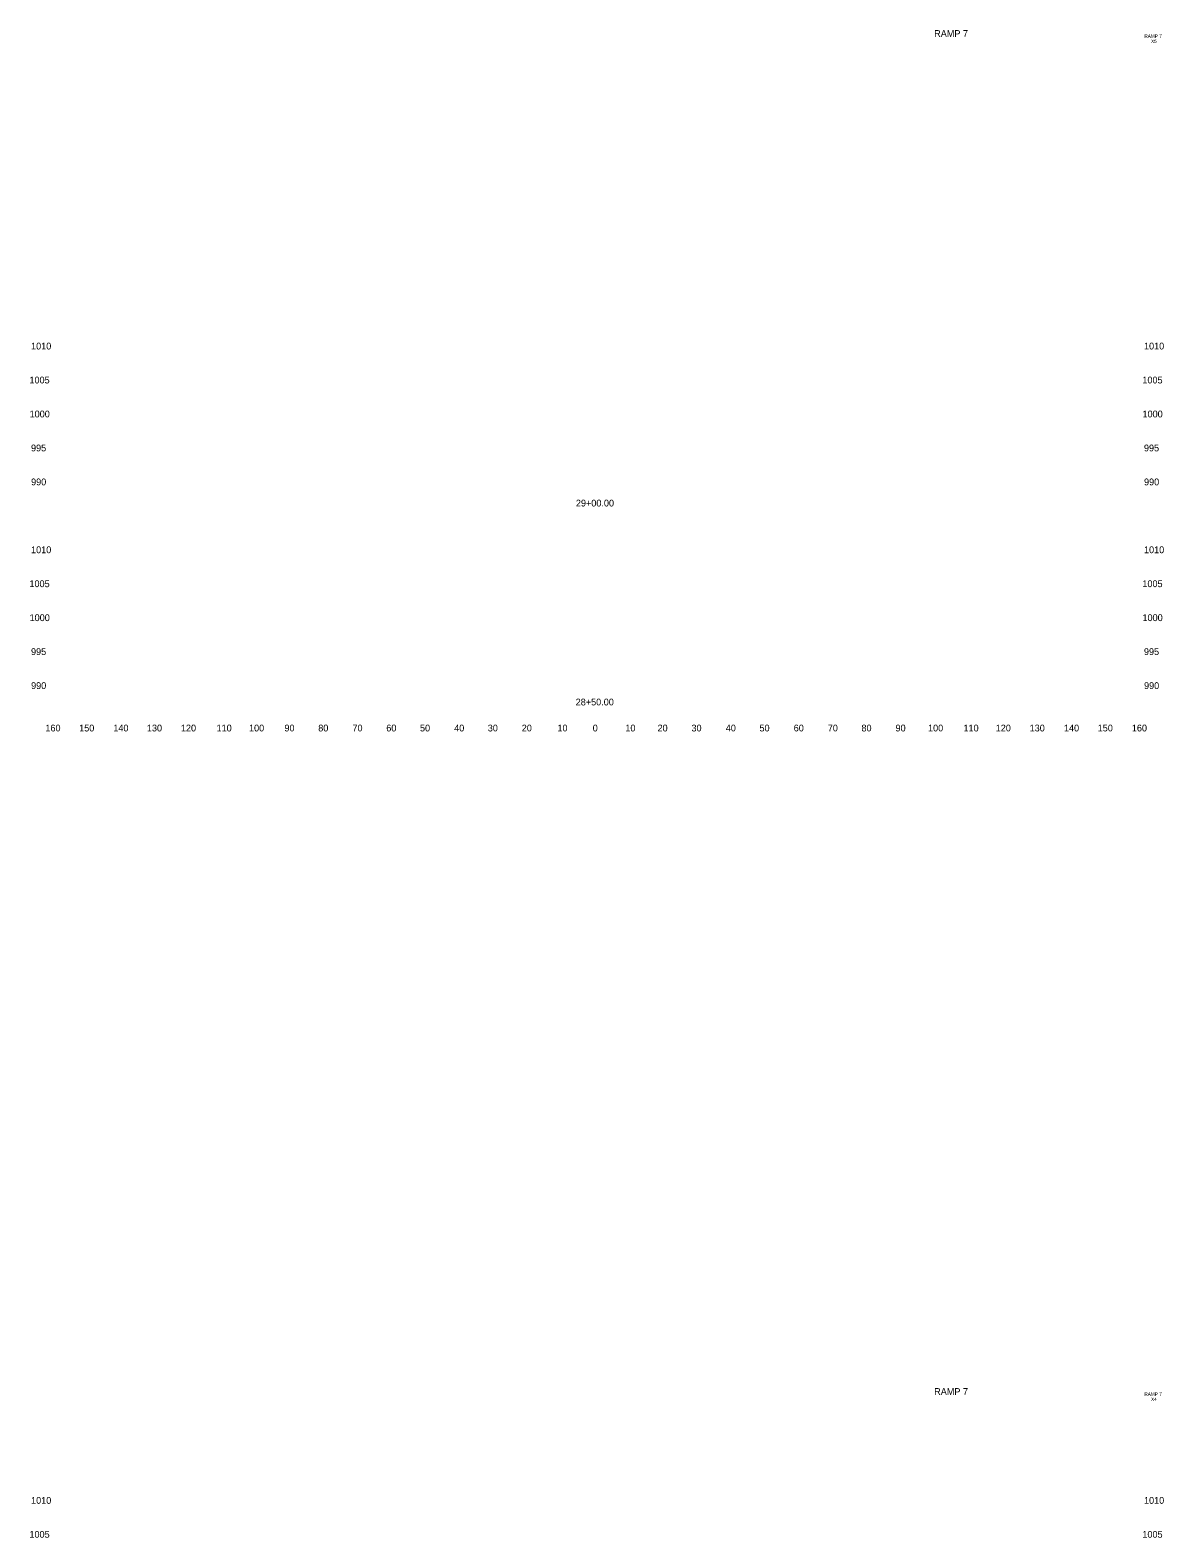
# Model space of a CAD drawing. Extents: x 4994 to 5701, y 4992 to 6804.
# Drawn here: x 4993.6 to 5327.5, y 6360 to 6804.1 of the extents above; entities that cross this region are included whole.
import ezdxf

# ---------------------------------------------------------------- set-up
doc = ezdxf.new("R2010")
doc.units = 0
for name, color, linetype in [('CLS_Search_Dist', 7, 'Continuous'), ('RD_XE_Ground', 7, 'Continuous'), ('UC_PD_Text', 7, 'Continuous')]:
    doc.layers.add(name, color=color, linetype=linetype)

msp = doc.modelspace()

# ---------------------------------------------------------------- texts
at = {"layer": 'CLS_Search_Dist'}
for s, p in [('1010', (4993.88, 6710)), ('1010', (5321.68, 6710)), ('1005', (4993.4, 6700)), ('1005', (5321.2, 6700)), ('1000', (4993.44, 6690)), ('1000', (5321.24, 6690)), ('995', (4993.86, 6680)), ('995', (5321.66, 6680)), ('990', (4993.89, 6670)), ('990', (5321.69, 6670)), ('1010', (4993.88, 6650)), ('1010', (5321.68, 6650)), ('1005', (4993.4, 6640)), ('1005', (5321.2, 6640)), ('1000', (4993.44, 6630)), ('1000', (5321.24, 6630)), ('995', (4993.86, 6620)), ('995', (5321.66, 6620)), ('990', (4993.89, 6610)), ('990', (5321.69, 6610)), ('160', (4998.1, 6597.5)), ('150', (5008.04, 6597.5)), ('140', (5018.1, 6597.5)), ('130', (5027.99, 6597.5)), ('120', (5038.01, 6597.5)), ('110', (5048.51, 6597.5)), ('100', (5058.07, 6597.5)), ('90', (5068.5, 6597.5)), ('80', (5078.46, 6597.5)), ('70', (5088.54, 6597.5)), ('60', (5098.5, 6597.5)), ('50', (5108.43, 6597.5)), ('40', (5118.5, 6597.5)), ('30', (5128.39, 6597.5)), ('20', (5138.4, 6597.5)), ('10', (5148.91, 6597.5)), ('0', (5159.3, 6597.5)), ('0', (5159.3, 6597.5)), ('10', (5168.91, 6597.5)), ('20', (5178.4, 6597.5)), ('30', (5188.39, 6597.5)), ('40', (5198.5, 6597.5)), ('50', (5208.43, 6597.5)), ('60', (5218.5, 6597.5)), ('70', (5228.54, 6597.5)), ('80', (5238.46, 6597.5)), ('90', (5248.5, 6597.5)), ('100', (5258.07, 6597.5)), ('110', (5268.51, 6597.5)), ('120', (5278.01, 6597.5)), ('130', (5287.99, 6597.5)), ('140', (5298.1, 6597.5)), ('150', (5308.04, 6597.5)), ('160', (5318.1, 6597.5)), ('1010', (4993.88, 6370)), ('1010', (5321.68, 6370)), ('1005', (4993.4, 6360)), ('1005', (5321.2, 6360))]:
    msp.add_text(s, height=2, dxfattribs=at).set_placement(p)
at = {"layer": 'RD_XE_Ground'}
for s, p in [('29+00.00', (5154.35, 6663.76)), ('28+50.00', (5154.29, 6605.16))]:
    msp.add_text(s, height=2, dxfattribs=at).set_placement(p)
at = {"layer": 'UC_PD_Text'}
for s, height, p in [('RAMP 7', 2, (5259.88, 6802.06)), ('RAMP 7', 1, (5321.78, 6801.8)), ('X5', 1, (5323.74, 6800.3)), ('RAMP 7', 2, (5259.88, 6402.06)), ('RAMP 7', 1, (5321.78, 6401.8)), ('X4', 1, (5323.74, 6400.3))]:
    msp.add_text(s, height=height, dxfattribs=at).set_placement(p)

doc.saveas('drawing.dxf')
